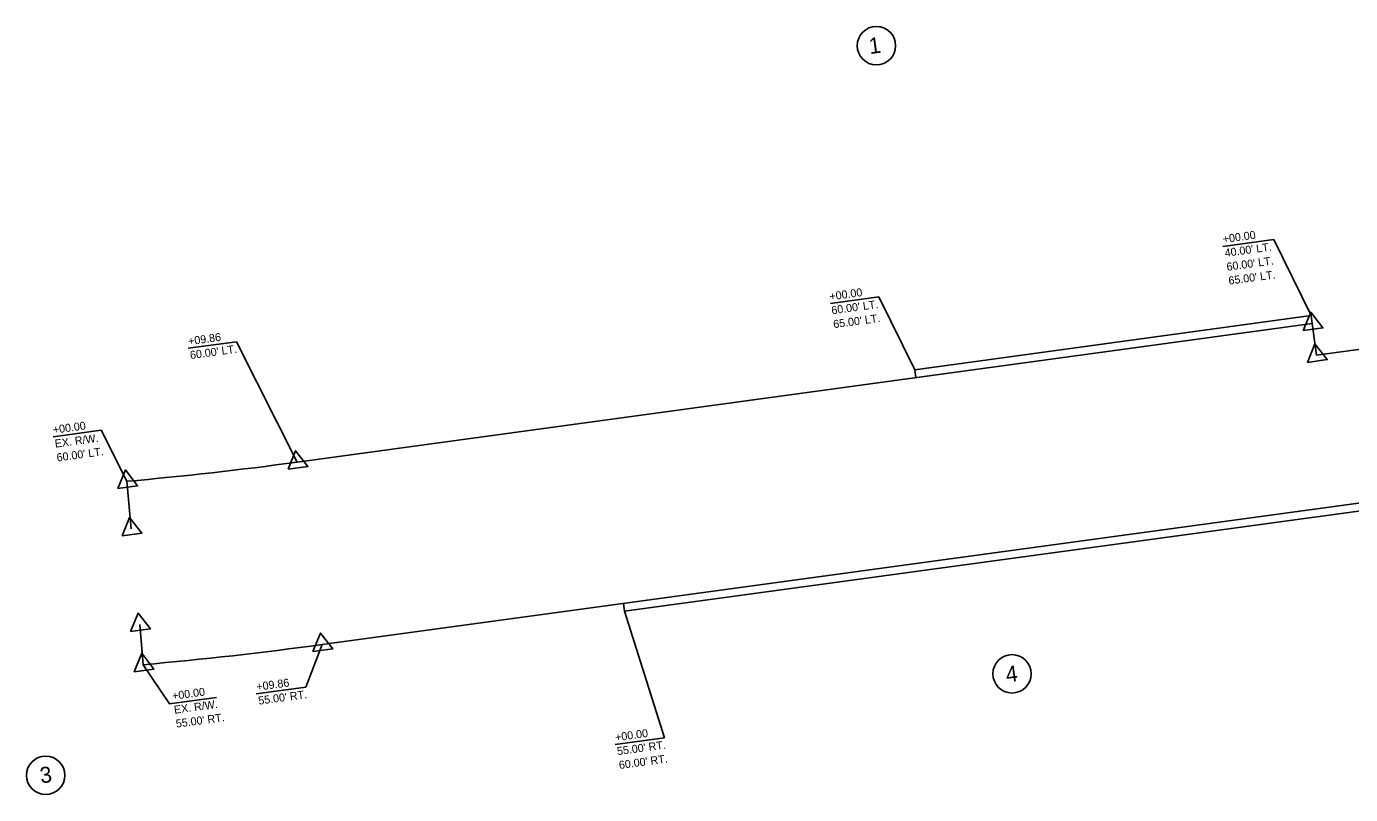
# Model space of a CAD drawing. Extents: x 2111254 to 2112709, y 581490 to 582407.
# Drawn here: x 2111254 to 2112082, y 581490 to 581970 of the extents above; entities that cross this region are included whole.
import ezdxf

# ---------------------------------------------------------------- set-up
doc = ezdxf.new("R2010")
doc.units = 0
for name, color, linetype in [('Prop Easement Construction', 7, 'Continuous'), ('Prop Easement Construction Station Offsets', 7, 'Continuous'), ('Prop Parcel Number CELL', 7, 'Continuous'), ('Prop Parcel Number Text', 7, 'Continuous'), ('Prop ROW Marker CELL', 7, 'Continuous'), ('Prop ROW RW Lines', 7, 'Continuous'), ('Prop ROW Station Offsets', 7, 'Continuous')]:
    doc.layers.add(name, color=color, linetype=linetype)

msp = doc.modelspace()

# ---------------------------------------------------------------- linework, layer by layer
at = {"layer": 'Prop Easement Construction'}
for p, q in [((2111809.32, 581755.58), (2112057.02, 581789.39)), ((2112057.02, 581789.39), (2112057.7, 581784.43)), ((2111809.32, 581755.58), (2111810, 581750.63)), ((2111628.06, 581604.69), (2112222.55, 581685.82)), ((2111627.38, 581609.64), (2111628.06, 581604.69))]:
    msp.add_line(p, q, dxfattribs=at)
at = {"layer": 'Prop Easement Construction Station Offsets'}
for p, q in [((2111786.84, 581801.12), (2111756.64, 581797)), ((2111652.87, 581525.74), (2111628.06, 581604.69)), ((2111652.87, 581525.74), (2111622.15, 581521.55))]:
    msp.add_line(p, q, dxfattribs=at)
msp.add_lwpolyline([(2111786.84, 581801.12), (2111809.32, 581755.58)], dxfattribs=at)
at = {"layer": 'Prop Parcel Number CELL'}
for p, q in [((2111785.41, 581958), (2111785.41, 581958)), ((2111870.15, 581565.64), (2111870.15, 581565.64)), ((2111266.29, 581502.27), (2111266.29, 581502.27))]:
    msp.add_line(p, q, dxfattribs=at)
for centre in [(2111785.41, 581958), (2111870.15, 581565.64), (2111266.29, 581502.27)]:
    msp.add_circle(centre, 12, dxfattribs=at)
at = {"layer": 'Prop ROW Marker CELL'}
for p, q in [((2112057.7, 581784.43), (2112057.7, 581784.43)), ((2112060.4, 581764.62), (2112060.4, 581764.62)), ((2111423.44, 581697.88), (2111423.44, 581697.88)), ((2111317.08, 581685.9), (2111317.08, 581685.9)), ((2111319.71, 581656.24), (2111319.71, 581656.24)), ((2111325.03, 581596.47), (2111325.03, 581596.47)), ((2111438.99, 581583.93), (2111438.99, 581583.93)), ((2111327.26, 581571.35), (2111327.26, 581571.35))]:
    msp.add_line(p, q, dxfattribs=at)
for points in [[(2112051.99, 581780.02), (2112056.73, 581791.57), (2112064.38, 581781.71)], [(2112054.7, 581760.21), (2112059.43, 581771.75), (2112067.08, 581761.9)], [(2111417.73, 581693.47), (2111422.46, 581705.01), (2111430.12, 581695.16)], [(2111311.37, 581681.48), (2111316.1, 581693.03), (2111323.76, 581683.17)], [(2111314.01, 581651.82), (2111318.74, 581663.37), (2111326.39, 581653.51)], [(2111319.32, 581592.06), (2111324.06, 581603.6), (2111331.71, 581593.75)], [(2111433.28, 581579.52), (2111438.01, 581591.07), (2111445.66, 581581.21)], [(2111321.56, 581566.94), (2111326.29, 581578.48), (2111333.94, 581568.63)]]:
    msp.add_lwpolyline(points, close=True, dxfattribs=at)
at = {"layer": 'Prop ROW RW Lines'}
for p, q in [((2111423.44, 581697.88), (2112057.7, 581784.43)), ((2112057.7, 581784.43), (2112060.4, 581764.62)), ((2112060.4, 581764.62), (2112209.03, 581784.9)), ((2111438.99, 581583.93), (2112221.87, 581690.77)), ((2111317.08, 581685.9), (2111319.71, 581656.24)), ((2111325.03, 581596.47), (2111327.26, 581571.35))]:
    msp.add_line(p, q, dxfattribs=at)
for radius in [2282.03, 2397.03]:
    msp.add_arc((2111114.87, 583958.95), radius, 275.08344, 277.77101, dxfattribs=at)
at = {"layer": 'Prop ROW Station Offsets'}
for p, q in [((2112033.75, 581836.86), (2112001.9, 581832.51)), ((2112033.75, 581836.86), (2112057.02, 581789.39)), ((2111385.54, 581773.09), (2111355.41, 581768.97)), ((2111385.54, 581773.09), (2111423.44, 581697.88)), ((2111301.02, 581717.76), (2111270.9, 581713.65)), ((2111301.02, 581717.76), (2111317.08, 581685.9)), ((2111428.77, 581557.3), (2111438.99, 581583.93)), ((2111343.61, 581546.9), (2111327.26, 581571.35)), ((2111428.77, 581557.3), (2111397.91, 581553.09)), ((2111372.96, 581550.9), (2111343.61, 581546.9))]:
    msp.add_line(p, q, dxfattribs=at)

# ---------------------------------------------------------------- texts
at = {"layer": 'Prop Easement Construction Station Offsets'}
for s, p in [('+00.00', (2111756.39, 581798.86)), ("60.00' LT.", (2111757.57, 581790.19)), ("65.00' LT.", (2111758.76, 581781.52)), ('+00.00', (2111622.46, 581523.48)), ("55.00' RT. ", (2111623.65, 581514.81)), ("60.00' RT.", (2111624.83, 581506.14))]:
    msp.add_text(s, height=5, rotation=7.77101, dxfattribs=at).set_placement(p)
at = {"layer": 'Prop Parcel Number Text'}
for s, p in [('1', (2111781.33, 581952.72)), ('4', (2111866.84, 581560.2)), ('3', (2111263.36, 581497.15))]:
    msp.add_text(s, height=10, rotation=7.77101, dxfattribs=at).set_placement(p)
at = {"layer": 'Prop ROW Station Offsets'}
for s, p in [('+00.00', (2112002.17, 581834.71)), ("40.00' LT.", (2112003.35, 581826.04)), ("60.00' LT.", (2112004.53, 581817.37)), ("65.00' LT.", (2112005.72, 581808.7)), ('+09.86', (2111355.65, 581770.9)), ("60.00' LT.", (2111356.83, 581762.23)), ('+00.00', (2111271.13, 581715.57)), ('EX. R/W.', (2111272.31, 581706.9)), ("60.00' LT.", (2111273.5, 581698.23)), ('+09.86', (2111398.31, 581555.04)), ('+00.00', (2111345.63, 581549.33)), ('EX. R/W.', (2111346.81, 581540.66)), ("55.00' RT.", (2111399.49, 581546.37)), ("55.00' RT.", (2111347.99, 581531.99))]:
    msp.add_text(s, height=5, rotation=7.77101, dxfattribs=at).set_placement(p)

doc.saveas('drawing.dxf')
